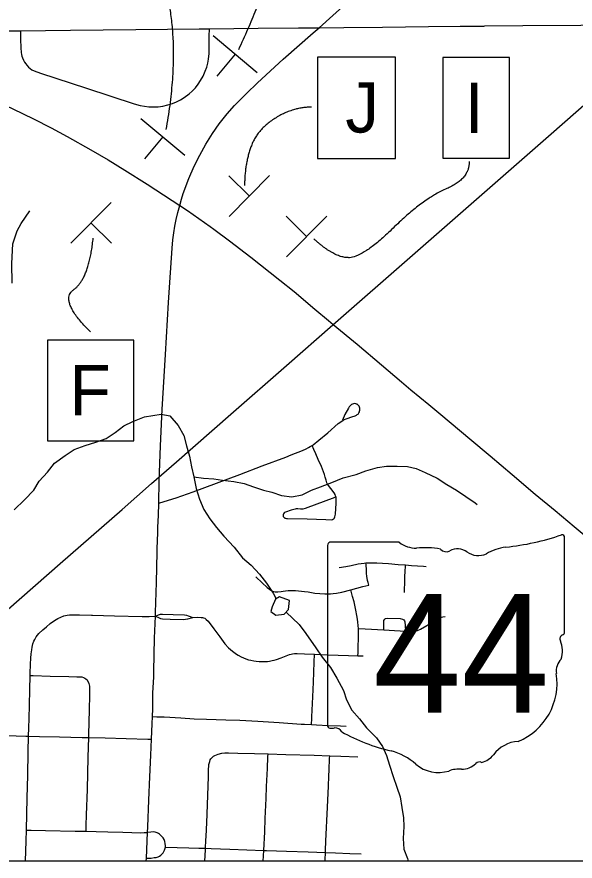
# Model space of a CAD drawing. Extents: x 0 to 34, y 0 to 22.
# Drawn here: x 4.256 to 5.809, y 4.299 to 6.648 of the extents above; entities that cross this region are included whole.
import ezdxf

# ---------------------------------------------------------------- set-up
doc = ezdxf.new("R2010")
doc.units = 0
for name, color, linetype in [('GM_X_City_Street', 7, 'Continuous'), ('GM_X_County_Road', 7, 'Continuous'), ('GM_X_Minor_Lake', 7, 'Continuous'), ('GM_X_Minor_River', 7, 'Continuous'), ('GM_X_Rail_Line', 7, 'Continuous'), ('GM_X_State_Route', 7, 'Continuous'), ('GM_X_State_Shield', 7, 'Continuous'), ('SH_Text', 7, 'Continuous'), ('SN_P_Signs', 7, 'Continuous')]:
    doc.layers.add(name, color=color, linetype=linetype)

msp = doc.modelspace()

# ---------------------------------------------------------------- linework, layer by layer
at = {"layer": 'GM_X_City_Street'}
for points in [[(4.2664, 6.6095), (4.2667, 6.5863), (4.2674, 6.5621), (4.2683, 6.5496), (4.2693, 6.5436), (4.2703, 6.5389), (4.2718, 6.5341), (4.2746, 6.528), (4.2779, 6.5222), (4.281, 6.5175), (4.2842, 6.5136), (4.2888, 6.5087), (4.293, 6.5049), (4.2981, 6.5013), (4.3041, 6.4981), (4.3224, 6.4915), (4.45, 6.4502), (4.5827, 6.4067), (4.5991, 6.4022), (4.6111, 6.3997), (4.6232, 6.3982), (4.637, 6.3977), (4.6492, 6.3984), (4.6628, 6.4004), (4.6763, 6.4034), (4.6894, 6.4076), (4.7008, 6.4122), (4.7117, 6.4178), (4.7221, 6.4243), (4.7357, 6.4342), (4.7437, 6.4413), (4.7531, 6.4514), (4.7607, 6.461), (4.7675, 6.4712), (4.7742, 6.4833), (4.7804, 6.4973), (4.7845, 6.5088), (4.7872, 6.5192), (4.7894, 6.5312), (4.7909, 6.5465), (4.7914, 6.5569), (4.7915, 6.5666), (4.7914, 6.5946), (4.7918, 6.6156)], [(4.6509, 5.2956), (4.6663, 5.2999), (4.6996, 5.3103), (4.7463, 5.3265), (4.8766, 5.3751), (4.9389, 5.3989), (5.004, 5.4234), (5.0196, 5.4293), (5.0509, 5.4422), (5.0606, 5.4465), (5.0675, 5.45), (5.0725, 5.4525), (5.0774, 5.4558), (5.0802, 5.4577), (5.0962, 5.4701), (5.121, 5.4913), (5.1503, 5.5167), (5.1634, 5.5256), (5.1691, 5.5285), (5.1753, 5.5309), (5.1881, 5.535), (5.1971, 5.5383), (5.2009, 5.5401), (5.2033, 5.5417), (5.2053, 5.5433), (5.2066, 5.545), (5.2079, 5.547), (5.2089, 5.549), (5.2097, 5.5514), (5.2103, 5.5543), (5.2103, 5.5574), (5.21, 5.5597), (5.2093, 5.5621), (5.2081, 5.5648), (5.2063, 5.5674), (5.2045, 5.5692), (5.2031, 5.5703), (5.2014, 5.5711), (5.1988, 5.5717), (5.1958, 5.5721), (5.1923, 5.5717), (5.19, 5.5707), (5.1874, 5.5694), (5.1853, 5.5679), (5.183, 5.566), (5.181, 5.5636), (5.1784, 5.5597), (5.1688, 5.5416), (5.1617, 5.5264)], [(5.1407, 5.3112), (5.0578, 5.2803), (5.0518, 5.2788), (5.049, 5.2786), (5.0456, 5.2788), (5.0378, 5.2797), (5.0329, 5.2793), (5.0301, 5.2788), (5.0197, 5.2757), (5.0034, 5.2705), (5.0008, 5.269), (4.9995, 5.2679), (4.9977, 5.2654), (4.9967, 5.2625), (4.9967, 5.2609), (4.9973, 5.2578), (4.9987, 5.2559), (5.0003, 5.2546), (5.002, 5.2536), (5.0038, 5.2531), (5.0059, 5.2527), (5.009, 5.2526), (5.064, 5.2518), (5.1153, 5.2495), (5.1304, 5.249), (5.1339, 5.2493), (5.1374, 5.2514), (5.1388, 5.2528), (5.1402, 5.2546), (5.1411, 5.2569), (5.1421, 5.2605), (5.1427, 5.2645), (5.1446, 5.2955), (5.1446, 5.3063), (5.1442, 5.3106), (5.1428, 5.3153), (5.1415, 5.3189), (5.1385, 5.3236), (5.1296, 5.336), (5.1229, 5.3446), (5.1201, 5.3484), (5.1185, 5.352), (5.1164, 5.3591), (5.1142, 5.3678), (5.1121, 5.3752), (5.1094, 5.3821), (5.1033, 5.3973), (5.0948, 5.4167), (5.0882, 5.4321), (5.0827, 5.4442), (5.0774, 5.4558)], [(5.1524, 5.1159), (5.1713, 5.1193), (5.1859, 5.1221), (5.2057, 5.126), (5.2139, 5.1274), (5.2223, 5.1284), (5.2273, 5.1287), (5.2315, 5.1289), (5.2575, 5.129), (5.2734, 5.1282), (5.2899, 5.1275), (5.3169, 5.1249), (5.3374, 5.1232), (5.3538, 5.122), (5.3873, 5.1198), (5.3951, 5.1194)], [(5.2351, 5.067), (5.2331, 5.0743), (5.2317, 5.0804), (5.2306, 5.0861), (5.23, 5.0908), (5.229, 5.1004), (5.2285, 5.1093), (5.2276, 5.1239), (5.2273, 5.1287)], [(5.3344, 5.0466), (5.3349, 5.058), (5.3353, 5.071), (5.3357, 5.0879), (5.3368, 5.1077), (5.3372, 5.1172), (5.3374, 5.1232)], [(4.921, 5.0898), (4.9382, 5.0732), (4.9525, 5.0603), (4.9587, 5.0556), (4.9627, 5.0527), (4.967, 5.0505), (4.9713, 5.049), (4.9746, 5.0484), (4.9783, 5.0484), (4.9818, 5.0486), (4.9918, 5.0498), (4.9971, 5.0507), (5.0034, 5.0515), (5.0112, 5.0521), (5.02, 5.0523), (5.0317, 5.0517), (5.0484, 5.0504), (5.0562, 5.0496), (5.0664, 5.0484), (5.0848, 5.0448)], [(5.0848, 5.0448), (5.1128, 5.0433), (5.121, 5.043), (5.1286, 5.0431), (5.1357, 5.0434), (5.1453, 5.0443), (5.1599, 5.0473), (5.1856, 5.0541), (5.2188, 5.0629), (5.2351, 5.067)], [(5.2051, 4.8704), (5.2054, 4.8788), (5.2059, 4.8962), (5.2066, 4.9182), (5.2066, 4.9328), (5.2061, 4.9464), (5.2058, 4.9542), (5.2048, 4.9653), (5.2031, 4.9777), (5.1986, 5.0024), (5.1942, 5.0205), (5.1903, 5.0358), (5.1856, 5.0541)], [(4.3179, 4.9328), (4.3287, 4.9426), (4.3385, 4.9515), (4.3493, 4.9603), (4.3612, 4.9687), (4.3705, 4.9744), (4.3784, 4.9781), (4.3873, 4.9814), (4.3958, 4.9836), (4.4028, 4.9843), (4.412, 4.9847), (4.4308, 4.9847), (4.4635, 4.9836), (4.4665, 4.9836), (4.5276, 4.9818), (4.6049, 4.98), (4.6247, 4.9799), (4.6415, 4.9809)], [(4.6415, 4.9809), (4.6501, 4.9846), (4.6554, 4.986), (4.6611, 4.9866), (4.6908, 4.9858), (4.7224, 4.9843), (4.7278, 4.9835), (4.7329, 4.9821), (4.746, 4.9772)], [(4.6415, 4.9809), (4.6501, 4.9767), (4.656, 4.9747), (4.6616, 4.9735), (4.6828, 4.9725), (4.7188, 4.9716), (4.7255, 4.9723), (4.7316, 4.9733), (4.746, 4.9772)], [(4.746, 4.9772), (4.7599, 4.9776), (4.7687, 4.9774), (4.7729, 4.9767), (4.7758, 4.9761), (4.7787, 4.975), (4.7833, 4.9717), (4.7884, 4.9664), (4.8044, 4.9456), (4.8206, 4.9229), (4.8347, 4.9041), (4.8453, 4.8924), (4.8559, 4.883), (4.8674, 4.8747), (4.8721, 4.8718), (4.8799, 4.8678), (4.8929, 4.8622), (4.9005, 4.8595), (4.907, 4.8579), (4.915, 4.8562), (4.9222, 4.8552), (4.9307, 4.8546), (4.9379, 4.8544), (4.9461, 4.8544), (4.9534, 4.855), (4.9592, 4.8558), (4.9663, 4.857), (4.9723, 4.8585), (4.9784, 4.8604), (4.9917, 4.8651), (5.0144, 4.8738), (5.0189, 4.8752), (5.023, 4.876), (5.0283, 4.8764), (5.0359, 4.8768), (5.0563, 4.8762), (5.0839, 4.8748), (5.1215, 4.8735), (5.1792, 4.8712), (5.2051, 4.8704), (5.2191, 4.8699)], [(5.2061, 4.9464), (5.2249, 4.9454), (5.2766, 4.9427), (5.2914, 4.9419), (5.3375, 4.9394), (5.3501, 4.9388), (5.3559, 4.9388), (5.362, 4.9392), (5.3665, 4.9401), (5.3708, 4.9412), (5.379, 4.9446), (5.3962, 4.9546), (5.4247, 4.9736), (5.4289, 4.9756), (5.434, 4.9774), (5.4415, 4.9791), (5.4477, 4.9796)], [(5.2766, 4.9427), (5.2766, 4.9562), (5.2766, 4.9641), (5.2773, 4.9687), (5.2797, 4.9727), (5.2821, 4.9745), (5.2866, 4.9756), (5.3225, 4.9738), (5.3287, 4.9728), (5.3327, 4.9705), (5.3347, 4.9681), (5.3358, 4.9652), (5.3365, 4.9544), (5.3375, 4.9394)], [(4.2806, 4.2991), (4.2825, 4.356), (4.2833, 4.3852), (4.2853, 4.4752), (4.2873, 4.537), (4.2877, 4.6034), (4.2887, 4.6464), (4.2893, 4.6703), (4.2903, 4.6964), (4.2912, 4.7333), (4.2923, 4.7754), (4.2934, 4.8156), (4.2936, 4.8213), (4.2944, 4.8467), (4.2953, 4.8641), (4.2963, 4.8759), (4.2977, 4.8872), (4.2991, 4.8947), (4.3012, 4.9034), (4.3037, 4.9113), (4.3061, 4.9161), (4.31, 4.9235), (4.3179, 4.9328)], [(5.0758, 4.6792), (5.0766, 4.6962), (5.0768, 4.7008), (5.0793, 4.7565), (5.081, 4.7967), (5.083, 4.8524), (5.0839, 4.8748)], [(4.2934, 4.8156), (4.3021, 4.8154), (4.3494, 4.8139), (4.401, 4.8128), (4.4232, 4.8123), (4.4309, 4.812), (4.4368, 4.8115), (4.4415, 4.8105), (4.4456, 4.8084), (4.4482, 4.8065), (4.4515, 4.8034), (4.4541, 4.7997)], [(4.4489, 4.3821), (4.4494, 4.398), (4.4502, 4.4275), (4.4524, 4.4985), (4.4534, 4.5438), (4.4548, 4.5877), (4.4553, 4.6158), (4.4562, 4.6432), (4.4564, 4.6518), (4.4582, 4.7199), (4.4588, 4.7307), (4.4592, 4.7509), (4.4597, 4.7754), (4.4595, 4.7806), (4.4589, 4.7862), (4.4582, 4.7901), (4.457, 4.7937), (4.4541, 4.7997)], [(4.6333, 4.7013), (4.6458, 4.7009), (4.6663, 4.7003), (4.712, 4.6975), (4.7496, 4.695), (4.7838, 4.6937), (4.8378, 4.6923), (4.8765, 4.6913), (4.9265, 4.6886), (4.9859, 4.6846), (5.0474, 4.6806), (5.0561, 4.6802), (5.0758, 4.6792), (5.0901, 4.6785), (5.1226, 4.6765), (5.1561, 4.6751), (5.1724, 4.6743)], [(4.1323, 4.6454), (4.135, 4.6477), (4.1376, 4.649), (4.1399, 4.6497), (4.1461, 4.6502), (4.1588, 4.6505), (4.1942, 4.6495), (4.2271, 4.6484), (4.2811, 4.6466), (4.2887, 4.6464), (4.3195, 4.6457), (4.3751, 4.6449), (4.4061, 4.6443), (4.4384, 4.6435), (4.4562, 4.6432), (4.5023, 4.6422), (4.5604, 4.6401), (4.621, 4.6386), (4.6306, 4.6382)], [(4.7794, 4.2991), (4.7809, 4.3303), (4.7811, 4.3347), (4.7821, 4.3571), (4.7826, 4.3678), (4.7845, 4.4064), (4.7855, 4.4295), (4.7872, 4.4823), (4.7889, 4.5337), (4.7895, 4.5507), (4.7905, 4.5677), (4.7927, 4.5767), (4.7944, 4.5807), (4.7962, 4.5836), (4.8003, 4.5883), (4.8037, 4.5909), (4.8066, 4.5928), (4.8158, 4.597)], [(4.8158, 4.597), (4.8263, 4.5994), (4.8349, 4.6002), (4.8447, 4.6006), (4.8705, 4.5999), (4.9172, 4.599), (4.9552, 4.598), (5.0042, 4.5961), (5.0832, 4.5938), (5.1265, 4.5922), (5.1576, 4.5911), (5.2047, 4.5895)], [(4.9415, 4.2991), (4.943, 4.3286), (4.9456, 4.3806), (4.9474, 4.4176), (4.9498, 4.4733), (4.951, 4.507), (4.953, 4.5564), (4.9548, 4.5897), (4.9552, 4.598)], [(5.114, 4.2991), (5.1142, 4.3029), (5.1147, 4.3228), (5.115, 4.3295), (5.116, 4.3545), (5.1201, 4.4496), (5.1231, 4.5075), (5.1242, 4.5356), (5.1248, 4.5531), (5.1262, 4.5849), (5.1265, 4.5922)], [(4.2833, 4.3852), (4.2961, 4.3849), (4.3356, 4.384), (4.4184, 4.3828), (4.4489, 4.3821), (4.4772, 4.3814), (4.5097, 4.3805), (4.5513, 4.3792), (4.6014, 4.3781), (4.6108, 4.3783), (4.6199, 4.3788)], [(4.6168, 4.307), (4.6296, 4.3077), (4.6386, 4.3087), (4.6441, 4.3096), (4.6491, 4.3109), (4.6532, 4.3128), (4.6569, 4.3154), (4.6604, 4.3189), (4.6629, 4.322), (4.6653, 4.326), (4.667, 4.3292), (4.6683, 4.3327), (4.6693, 4.3381), (4.6694, 4.3413), (4.6688, 4.3484), (4.6677, 4.3541), (4.6658, 4.359), (4.6629, 4.3639), (4.6608, 4.3664), (4.6571, 4.3707), (4.6535, 4.3741), (4.65, 4.3763), (4.6463, 4.378), (4.6412, 4.3795), (4.6368, 4.3802), (4.6293, 4.3797), (4.6199, 4.3788)], [(4.6693, 4.3381), (4.7345, 4.3364), (4.7622, 4.3355), (4.7811, 4.3347), (4.7964, 4.3341), (4.8488, 4.3319), (4.943, 4.3286), (4.9506, 4.3284), (5.006, 4.3269), (5.0663, 4.3251), (5.1147, 4.3228), (5.143, 4.3222), (5.1824, 4.3207), (5.2142, 4.3198)]]:
    msp.add_lwpolyline(points, dxfattribs=at)
at = {"layer": 'GM_X_County_Road'}
for points in [[(5.5575, 6.6231), (5.6638, 6.6243), (5.8252, 6.6251), (6.037, 6.627), (6.051, 6.627)], [(3.9074, 6.6058), (3.9097, 6.6056), (3.9324, 6.6051), (3.9561, 6.6047), (4.0655, 6.6077), (4.2347, 6.6093), (4.2664, 6.6095)], [(4.2664, 6.6095), (4.4055, 6.6111), (4.5869, 6.6137), (4.7631, 6.6154), (4.7918, 6.6156)], [(4.7918, 6.6156), (4.9279, 6.6169), (5.0397, 6.6179), (5.0969, 6.6184)], [(5.0969, 6.6184), (5.1661, 6.619), (5.2731, 6.6201), (5.4017, 6.6214), (5.4897, 6.6224)], [(5.4897, 6.6224), (5.555, 6.623), (5.5575, 6.6231)]]:
    msp.add_lwpolyline(points, dxfattribs=at)
at = {"layer": 'GM_X_Minor_Lake'}
msp.add_line((4.9759, 5.0281), (4.9667, 5.0071), dxfattribs=at)
msp.add_lwpolyline([(4.9667, 5.0071), (4.963, 4.9937), (4.9764, 4.9835), (5, 4.9866), (5.0122, 4.9991), (5.0148, 5.0247), (4.9872, 5.0348), (4.9759, 5.0281)], dxfattribs=at)
at = {"layer": 'GM_X_Minor_River'}
for points in [[(4.2488, 5.2768), (4.2778, 5.3047), (4.3031, 5.3316), (4.318, 5.3564), (4.3414, 5.3814), (4.361, 5.4063), (4.391, 5.4275), (4.4154, 5.4449), (4.4466, 5.4557), (4.4758, 5.4646), (4.505, 5.4754), (4.5295, 5.4918), (4.5539, 5.5101), (4.5793, 5.5228), (4.6114, 5.5355), (4.6577, 5.5426), (4.6814, 5.5382), (4.7054, 5.5109), (4.7208, 5.4836), (4.7278, 5.4552), (4.7366, 5.4259), (4.7417, 5.3965), (4.7486, 5.3681), (4.7547, 5.3359), (4.7645, 5.3066), (4.7762, 5.2773), (4.7935, 5.2519), (4.8118, 5.2274), (4.8319, 5.203), (4.8607, 5.1729), (4.8837, 5.1428), (4.9076, 5.1222), (4.9316, 5.0978), (4.9508, 5.0724), (4.9691, 5.0451), (4.978, 5.0293)], [(4.7486, 5.3681), (4.7752, 5.3646), (4.8046, 5.3631), (4.8283, 5.3595), (4.8596, 5.3552), (4.889, 5.3498), (4.9146, 5.3406), (4.9422, 5.3314), (4.9659, 5.326), (4.9925, 5.3168), (5.021, 5.3124), (5.0503, 5.3185), (5.0757, 5.3311), (5.1012, 5.3409), (5.1323, 5.3526), (5.1643, 5.3653), (5.2002, 5.3753), (5.2266, 5.3851), (5.2596, 5.394), (5.2842, 5.3981), (5.3145, 5.3984), (5.3429, 5.3969), (5.3666, 5.3914), (5.3923, 5.3803), (5.4256, 5.3646), (5.4524, 5.3469), (5.479, 5.331), (5.5048, 5.3133), (5.5315, 5.2965), (5.5363, 5.2918)], [(5.0056, 4.9923), (5.0411, 4.9576), (5.0603, 4.9322), (5.0882, 4.8927), (5.1055, 4.8663), (5.1286, 4.8381), (5.1459, 4.8079), (5.1653, 4.774), (5.1731, 4.7475), (5.1876, 4.7192), (5.2097, 4.6947), (5.2289, 4.6703), (5.2567, 4.6421), (5.273, 4.6176), (5.2847, 4.5931), (5.2926, 4.5657), (5.3033, 4.5345), (5.3131, 4.5051), (5.3229, 4.4777), (5.327, 4.4483), (5.3321, 4.4199), (5.3323, 4.3952), (5.3308, 4.362), (5.333, 4.3326), (5.3428, 4.3061), (5.3447, 4.2991)]]:
    msp.add_lwpolyline(points, dxfattribs=at)
at = {"layer": 'GM_X_Rail_Line'}
for points in [[(4.631, 5.3498), (4.7, 5.4104), (4.8512, 5.5428), (5.0065, 5.6787), (5.1355, 5.7912), (5.3567, 5.9853), (5.7346, 6.3169), (6.0085, 6.5567), (6.1878, 6.7145), (6.2934, 6.806), (6.5822, 7.0593), (6.7081, 7.1697), (6.8704, 7.3121), (7.0343, 7.4557), (7.122, 7.532), (7.1883, 7.5902)], [(4.2429, 5.9073), (4.2421, 5.962), (4.2451, 6.0167), (4.2576, 6.053), (4.2685, 6.0735), (4.2921, 6.109)], [(3.4309, 4.2991), (3.4764, 4.3387), (3.6805, 4.5174), (3.8887, 4.6992), (4.1252, 4.9071), (4.1549, 4.9332), (4.3767, 5.1271), (4.5491, 5.2778), (4.631, 5.3498)]]:
    msp.add_lwpolyline(points, dxfattribs=at)
at = {"layer": 'GM_X_State_Route'}
msp.add_line((5.123, 5.8037), (5.1361, 5.7926), dxfattribs=at)
for points in [[(5.0969, 6.6184), (5.173, 6.6866), (5.2826, 6.7852), (5.3265, 6.8246), (5.3415, 6.838), (5.3555, 6.8503), (5.3622, 6.8566), (5.3958, 6.8865), (5.5391, 7.0146), (5.5409, 7.0162)], [(4.8954, 6.4348), (4.9257, 6.4645), (4.9968, 6.5308), (5.0805, 6.604), (5.0969, 6.6184)], [(3.7061, 6.601), (3.7571, 6.5856), (3.789, 6.5753), (3.826, 6.5629), (3.8615, 6.5511), (3.8991, 6.5378), (3.9389, 6.5233), (3.9911, 6.5035), (4.0396, 6.484), (4.092, 6.4614), (4.1589, 6.4322), (4.207, 6.4103), (4.245, 6.3925), (4.3023, 6.3646), (4.3522, 6.3392), (4.396, 6.3156), (4.4624, 6.2784), (4.5103, 6.2504), (4.5571, 6.2217), (4.6188, 6.1826), (4.6879, 6.1377), (4.7092, 6.1238)], [(4.7092, 6.1238), (4.7142, 6.1414), (4.7193, 6.157), (4.7351, 6.1988), (4.7499, 6.2328), (4.7648, 6.2632), (4.7821, 6.2942), (4.8007, 6.3243), (4.8192, 6.3508), (4.8412, 6.3786), (4.8615, 6.4017), (4.8954, 6.4348)], [(4.6784, 5.854), (4.6816, 5.9091), (4.6881, 6.005), (4.6904, 6.028), (4.693, 6.0476), (4.6961, 6.0661), (4.6996, 6.0848), (4.7038, 6.104), (4.7092, 6.1238)], [(4.7092, 6.1238), (4.7313, 6.1094), (4.794, 6.0649), (4.804, 6.0575)], [(4.804, 6.0575), (4.848, 6.025), (4.9072, 5.9796), (4.9877, 5.9161), (5.0278, 5.8841), (5.0853, 5.8355), (5.123, 5.8037)], [(4.6333, 4.7013), (4.6342, 4.7225), (4.6344, 4.735), (4.6343, 4.7411), (4.6343, 4.7473), (4.6348, 4.7612), (4.6347, 4.7658), (4.6349, 4.7674), (4.6371, 4.8108), (4.6372, 4.8279), (4.6395, 4.9194), (4.6415, 4.9809), (4.6418, 4.9908), (4.6444, 5.0747), (4.6468, 5.1585), (4.6469, 5.1694), (4.6481, 5.2126), (4.6488, 5.2281), (4.65, 5.2605), (4.6509, 5.2956), (4.6526, 5.3568), (4.6558, 5.4546), (4.6608, 5.5554), (4.6699, 5.709), (4.6784, 5.854)], [(5.1361, 5.7926), (5.2026, 5.7372), (5.2701, 5.6803), (5.3257, 5.6329), (5.3518, 5.611), (5.4025, 5.5699), (5.436, 5.5418), (5.5164, 5.4741), (5.5726, 5.427), (5.6343, 5.3748), (5.6982, 5.3204), (5.7531, 5.275), (5.8066, 5.2303), (5.8677, 5.1793)], [(4.6163, 4.2991), (4.6168, 4.307), (4.6199, 4.3788), (4.6206, 4.3944), (4.6236, 4.469), (4.6265, 4.534), (4.6293, 4.5941), (4.6306, 4.6382), (4.6325, 4.6807), (4.6333, 4.7013)]]:
    msp.add_lwpolyline(points, dxfattribs=at)
at = {"layer": 'GM_X_State_Shield'}
for p, q in [((5.7798, 4.9369), (5.7798, 5.1986)), ((5.1206, 5.1776), (5.1206, 4.6773)), ((5.3201, 5.1862), (5.1271, 5.1862)), ((5.7797, 4.937), (5.7798, 4.9369))]:
    msp.add_line(p, q, dxfattribs=at)
for centre, radius, start, end in [((5.545, 5.8683), 0.699, 275.8445, 288.9065), ((5.7725, 5.1997), 0.00734, 351.8621, 97.738), ((5.1282, 5.1787), 0.00764, 98.1301, 188.1301), ((5.3661, 5.2443), 0.0741, 231.6195, 271.1119), ((5.3907, 4.9054), 0.2659, 80.4867, 94.9883), ((5.6341, 5.0334), 0.1406, 97.3462, 120.7689), ((5.451, 5.1813), 0.0214, 219.7921, 297.1024), ((5.4824, 5.1235), 0.0444, 54.4667, 119.1411), ((5.5398, 5.2028), 0.0534, 233.8562, 294.8282), ((5.772, 4.9359), 0.00785, 289.6038, 7.7341), ((5.7781, 4.9177), 0.0114, 107.944, 210.337), ((5.7058, 4.8846), 0.0682, 340.033, 23.6496), ((5.8061, 4.8274), 0.0496, 136.8065, 186.9296), ((5.5841, 4.7941), 0.1748, 292.3089, 8.9858), ((5.1282, 4.6762), 0.0077, 171.9584, 258.3066), ((5.1294, 4.7274), 0.0588, 267.339, 280.6039), ((5.1414, 4.6485), 0.0212, 29.7484, 93.2717), ((5.4091, 5.098), 0.5048, 240.4129, 257.1985), ((5.6579, 4.5369), 0.0958, 94.4031, 142.5768), ((5.2586, 4.4526), 0.1579, 47.1842, 75.836), ((5.5365, 4.6289), 0.0565, 282.8732, 323.2771), ((5.4294, 4.646), 0.1002, 230.7004, 286.2918), ((5.4946, 4.6085), 0.0534, 268.777, 315.5493), ((5.5429, 4.5601), 0.015, 65.7517, 132.6484), ((5.4873, 4.473), 0.0824, 85.6951, 111.2099)]:
    msp.add_arc(centre, radius, start, end, dxfattribs=at)
at = {"layer": 'SH_Text'}
for points in [[(1.6712, 21.2991), (18.6712, 21.2991), (18.6712, 4.2991), (1.6712, 4.2991)], [(5.0922, 6.2545), (5.3096, 6.2545), (5.3096, 6.5365), (5.0922, 6.5365)], [(5.441, 6.2549), (5.6268, 6.2549), (5.6268, 6.5355), (5.441, 6.5355)], [(4.3418, 5.4691), (4.5813, 5.4691), (4.5813, 5.7491), (4.3418, 5.7491)]]:
    msp.add_lwpolyline(points, close=True, dxfattribs=at)
for points in [[(4.7476, 7.3021), (4.9036, 7.3021), (5.0431, 7.1726), (4.9933, 6.8204), (4.8728, 6.5567)], [(4.362, 6.9738), (4.5413, 6.9738), (4.6508, 6.8409), (4.7073, 6.5319), (4.6706, 6.3348)], [(5.0757, 6.3973), (5.0244, 6.3973), (4.9239, 6.3346), (4.8897, 6.2359), (4.8897, 6.179)], [(5.5146, 6.246), (5.5146, 6.1966), (5.3875, 6.1435), (5.2187, 5.9783), (5.139, 5.9783), (5.0822, 6.0308)], [(4.4613, 5.7716), (4.3721, 5.859), (4.4575, 5.9205), (4.4686, 6.0329)]]:
    msp.add_open_spline(points, degree=2, dxfattribs=at)
at = {"layer": 'SN_P_Signs'}
for p, q in [((4.8019, 6.5962), (4.9249, 6.4938)), ((4.8634, 6.545), (4.8123, 6.4835)), ((4.6007, 6.366), (4.7237, 6.2637)), ((4.6622, 6.3148), (4.611, 6.2533)), ((4.9028, 6.1501), (4.8459, 6.2064)), ((4.9591, 6.207), (4.8466, 6.0932)), ((4.4062, 6.0183), (4.5187, 6.132)), ((5.0622, 6.0372), (5.0053, 6.0934)), ((5.1184, 6.0941), (5.0059, 5.9803)), ((4.4625, 6.0751), (4.5193, 6.0189))]:
    msp.add_line(p, q, dxfattribs=at)

# ---------------------------------------------------------------- texts
at = {"layer": 'GM_X_State_Shield'}
msp.add_text('44', height=0.32959, dxfattribs=at).set_placement((5.2471, 4.7126))
at = {"layer": 'SH_Text'}
for s, p in [('J', (5.1699, 6.3265)), ('I', (5.5022, 6.3255)), ('F', (4.403, 5.5398))]:
    msp.add_text(s, height=0.14, dxfattribs=at).set_placement(p)

doc.saveas('drawing.dxf')
